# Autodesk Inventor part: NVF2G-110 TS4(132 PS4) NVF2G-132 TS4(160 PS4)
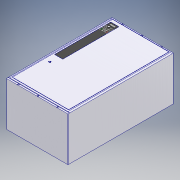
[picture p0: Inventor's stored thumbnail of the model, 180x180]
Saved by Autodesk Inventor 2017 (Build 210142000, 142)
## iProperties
Part Number: NVF2G-110 TS4(132 PS4) NVF2G-132 TS4(160 PS4)
Material: Типовые
Document SubType Name: Modeling
Designer: RSagdiev
Density: 1 g/cm^3
Appearance: По умолчанию
Author: RSagdiev
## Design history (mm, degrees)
sketch "Эскиз1"
  geometry: L1 (0, 0)-(44.679, 0) reference; L2 (0, 0)-(0, 56.035) reference; L3 (0, 0)-(807, 0); L4 (807, 0)-(807, 336.6); L5 (807, 336.6)-(0, 336.6); L6 (0, 336.6)-(0, 0)
  constraints: 12 end point, 3 horizontal, 2 parallel, 2 vertical, 1 perpendicular
  dimensions: "d0" = 807 distance of L5.end L4.end; "d1" = 336.6 distance of L4.end L3.end
extrude "Выдавливание1" new body sketch "Эскиз1" stored distance "d2" = 470; taper "d3" = 0 deg
sketch "Эскиз2"
  geometry: L1 (0, 0)-(0, 807) reference; L2 (470, 0)-(470, 807) reference; L3 (0, 807)-(150, 807); L4 (470, 807)-(470, 795); L5 (470, 0)-(320, 0); L6 (0, 0)-(0, 12); L7 (0, 807)-(470, 807) reference; L8 (0, 807)-(150, 807); L9 (150, 807)-(150, 795); L10 (150, 795)-(0, 795); L11 (0, 795)-(0, 807); L12 (470, 807)-(320, 807); L13 (320, 807)-(320, 795); L14 (320, 795)-(470, 795); L15 (470, 795)-(470, 807); L16 (0, 0)-(470, 0) reference; L17 (0, 0)-(150, 0); L18 (150, 0)-(150, 12); L19 (150, 12)-(0, 12); L20 (0, 12)-(0, 0); L21 (470, 0)-(320, 0); L22 (320, 0)-(320, 12); L23 (320, 12)-(470, 12); L24 (470, 12)-(470, 0); L25 (150, 807)-(320, 807); L26 (0, 795)-(0, 807); L27 (320, 807)-(470, 807); L28 (470, 795)-(470, 12); L29 (320, 0)-(150, 0); L30 (470, 12)-(470, 0); L31 (150, 0)-(0, 0); L32 (0, 12)-(0, 795); L33 (150, 795)-(320, 795); L34 (150, 12)-(320, 12); 1 further point
  constraints: 60 end point, 26 parallel, 13 perpendicular, 7 horizontal
  dimensions: "d4" = 150 distance of L9.end L10.end; "d5" = 12 distance of L3.end L9.end; "d6" = 150 distance of L4.end L13.end; "d7" = 12 distance of L13.end L12.end; "d8" = 150 distance of L6.end L18.end; "d9" = 12 distance of L18.end L17.end; "d10" = 150 distance of L22.end L23.end; "d11" = 12 distance of L5.end L22.end
extrude "Выдавливание2" new body sketch "Эскиз2" distance "d12" = 4; taper "d13" = 0 deg
sketch "Эскиз3"
  geometry: L1 (450, 25)-(450, 791); L2 (20, 791)-(450, 791); L3 (20, 791)-(20, 25); L4 (20, 791)-(450, 791); L5 (20, 25)-(450, 25); L6 (0, 795)-(0, 12) reference; L7 (470, 12)-(470, 795) reference; L8 (0, 807)-(470, 807) reference; L9 (0, 0)-(470, 0) reference; 1 further point
  constraints: 11 end point, 2 perpendicular, 1 horizontal
  dimensions: "d162" = 20 distance between parallel lines of L6 L3 (derived); "d164" = 20 distance between parallel lines of L7 L1; "d203" = 16 distance between parallel lines of L2 L8; "d204" = 25 distance between parallel lines of L9 L5
extrude "Выдавливание3" new body sketch "Эскиз3" distance "d17" = 2; taper "d18" = 0 deg
sketch "Эскиз4"
  geometry: L1 (91, 767)-(32, 767); L2 (30, 765)-(30, 339); L3 (32, 337)-(91, 337); L4 (93, 339)-(93, 765); L5 (0, 807)-(470, 807) reference; L6 (0, 795)-(0, 12) reference; A1 r 2 centre (32, 765) between (32, 767) and (30, 765); A2 r 2 centre (91, 765) between (93, 765) and (91, 767); A3 r 2 centre (91, 339) between (91, 337) and (93, 339); A4 r 2 centre (32, 339) between (30, 339) and (32, 337); 6 further points
  constraints: 8 end point, 8 point on circle, 8 tangent, 6 point on line, 4 centre point, 3 equal radius, 2 parallel, 1 horizontal, 1 perpendicular
  dimensions: "d20" = 63 distance of point (93, 337) point (30, 337); "d21" = 430 distance of point (30, 337) point (30, 767); "d24" = 2 radius of A1; "d165" = 40 distance between parallel lines of L5 L1; "d166" = 30 distance between parallel lines of L6 L2
extrude "Выдавливание4" cut sketch "Эскиз4" distance "d25" = 0.6; taper "d26" = 0 deg
sketch "Эскиз5"
  geometry: L1 (0, 807)-(470, 807) reference; L2 (0, 0)-(0, 807) reference; L3 (470, 807)-(470, 0) reference; L4 (0, 0)-(470, 0) reference; C1 r 5 at (85, 801); C2 r 5 at (235, 801); C3 r 5 at (85, 6); C4 r 5 at (235, 6); C5 r 5 at (385, 801); C6 r 5 at (385, 6); 1 further point
  constraints: 6 centre point
  dimensions: "d27" = 10 diameter of C1; "d28" = 6 distance from line of C1.centre L1; "d30" = 10 diameter of C2; "d31" = 6 distance from line of C2.centre L1; "d33" = 10 diameter of C3; "d34" = 6 distance from line of L4 C3.centre; "d36" = 10 diameter of C4; "d38" = 6 distance from line of C4.centre L4; "d169" = 150 distance of C1.centre C2.centre; "d172" = 150 distance of C4.centre C3.centre (derived); "d205" = 10 diameter of C5; "d206" = 150 distance of C5.centre C2.centre (derived); "d207" = 10 diameter of C6; "d208" = 150 distance of C6.centre C4.centre (derived); "d209" = 470 distance between parallel lines of L3 L2 (derived); "d210" = 85 distance from line of L2 C1.centre (derived); "d211" = 85 distance from line of L2 C3.centre (derived)
extrude "Выдавливание5" cut sketch "Эскиз5" stored distance "d39" = 0.6; taper "d40" = 0 deg
sketch "Эскиз6"
  geometry: L1 (30, 676)-(30, 732); L2 (91, 674)-(32, 674); L3 (93, 765)-(93, 732); L4 (32, 767)-(91, 767); L5 (30, 676)-(30, 765); L6 (30, 732)-(93, 732); L7 (93, 765)-(93, 732); L8 (30, 732)-(30, 765); L9 (93, 732)-(93, 676); L10 (43.5, 743)-(79.5, 743); L11 (81.5, 745)-(81.5, 755); L12 (79.5, 757)-(43.5, 757); L13 (41.5, 755)-(41.5, 745); L14 (41.5, 743)-(81.5, 757); L15 (81.5, 743)-(41.5, 757); L16 (61.5, 720.5)-(61.5, 685.857); L17 (53.25, 720.5)-(53.25, 685.857); L18 (69.75, 685.857)-(69.75, 720.5); L19 (47, 727)-(36, 727); L20 (35, 726)-(35, 715); L21 (36, 714)-(47, 714); L22 (48, 715)-(48, 726); L23 (48, 727)-(35, 714); L24 (35, 727)-(48, 714); L25 (81.5, 745)-(81.5, 680.5); L26 (41.5, 720.5)-(88.409, 720.5); L27 (39.654, 703.179)-(85.729, 703.179); L28 (39.654, 685.857)-(84.963, 685.857); L29 (88, 715)-(88, 726); L30 (76, 714)-(87, 714); L31 (88, 727)-(75, 714); L32 (75, 727)-(88, 714); L33 (75, 726)-(75, 715); L34 (87, 727)-(76, 727); L35 (88, 697.679)-(88, 708.679); L36 (76, 696.679)-(87, 696.679); L37 (88, 709.679)-(75, 696.679); L38 (75, 709.679)-(88, 696.679); L39 (75, 708.679)-(75, 697.679); L40 (87, 709.679)-(76, 709.679); L41 (88, 680.357)-(88, 691.357); L42 (76, 679.357)-(87, 679.357); L43 (88, 692.357)-(75, 679.357); L44 (75, 692.357)-(88, 679.357); L45 (75, 691.357)-(75, 680.357); L46 (87, 692.357)-(76, 692.357); L47 (48, 680.357)-(48, 691.357); L48 (36, 679.357)-(47, 679.357); L49 (48, 692.357)-(35, 679.357); L50 (35, 692.357)-(48, 679.357); L51 (35, 691.357)-(35, 680.357); L52 (47, 692.357)-(36, 692.357); L53 (48, 697.679)-(48, 708.679); L54 (36, 696.679)-(47, 696.679); L55 (48, 709.679)-(35, 696.679); L56 (35, 709.679)-(48, 696.679); L57 (35, 708.679)-(35, 697.679); L58 (47, 709.679)-(36, 709.679); L59 (91, 674)-(32, 674); L60 (0, 807)-(470, 807) reference; L61 (0, 793)-(0, 14); L62 (93, 732)-(93, 676); C1 r 6.5 at (61.5, 720.5); C2 r 6.5 at (61.5, 685.857); C3 r 6.5 at (61.5, 703.179); A1 r 2 centre (43.5, 755) between (43.5, 757) and (41.5, 755); A2 r 2 centre (79.5, 755) between (81.5, 755) and (79.5, 757); A3 r 2 centre (79.5, 745) between (79.5, 743) and (81.5, 745); A4 r 2 centre (43.5, 745) between (41.5, 745) and (43.5, 743); A5 r 8.25 centre (61.5, 720.5) between (69.75, 720.5) and (53.25, 720.5); A6 r 8.25 centre (61.5, 685.857) between (53.25, 685.857) and (69.75, 685.857); A7 r 1 centre (47, 726) between (48, 726) and (47, 727); A8 r 1 centre (47, 715) between (47, 714) and (48, 715); A9 r 1 centre (36, 715) between (35, 715) and (36, 714); A10 r 1 centre (36, 726) between (36, 727) and (35, 726); A11 r 1 centre (87, 715) between (87, 714) and (88, 715); A12 r 1 centre (87, 726) between (88, 726) and (87, 727); A13 r 1 centre (76, 726) between (76, 727) and (75, 726); A14 r 1 centre (76, 715) between (75, 715) and (76, 714); A15 r 1 centre (87, 697.679) between (87, 696.679) and (88, 697.679); A16 r 1 centre (87, 708.679) between (88, 708.679) and (87, 709.679); A17 r 1 centre (76, 708.679) between (76, 709.679) and (75, 708.679); A18 r 1 centre (76, 697.679) between (75, 697.679) and (76, 696.679); A19 r 1 centre (87, 680.357) between (87, 679.357) and (88, 680.357); A20 r 1 centre (87, 691.357) between (88, 691.357) and (87, 692.357); A21 r 1 centre (76, 691.357) between (76, 692.357) and (75, 691.357); A22 r 1 centre (76, 680.357) between (75, 680.357) and (76, 679.357); A23 r 1 centre (47, 680.357) between (47, 679.357) and (48, 680.357); A24 r 1 centre (47, 691.357) between (48, 691.357) and (47, 692.357); A25 r 1 centre (36, 691.357) between (36, 692.357) and (35, 691.357); A26 r 1 centre (36, 680.357) between (35, 680.357) and (36, 679.357); A27 r 1 centre (47, 697.679) between (47, 696.679) and (48, 697.679); A28 r 1 centre (47, 708.679) between (48, 708.679) and (47, 709.679); A29 r 1 centre (36, 708.679) between (36, 709.679) and (35, 708.679); A30 r 1 centre (36, 697.679) between (35, 697.679) and (36, 696.679); A31 r 2 centre (32, 765) between (32, 767) and (30, 765); A32 r 2 centre (91, 765) between (93, 765) and (91, 767); A33 r 2 centre (91, 676) between (91, 674) and (93, 676); A34 r 2 centre (32, 676) between (30, 676) and (32, 674); 15 further points
  constraints: 124 end point, 70 tangent, 68 point on circle, 67 point on line, 37 centre point, 21 equal radius, 15 midpoint, 15 parallel, 11 horizontal, 7 collinear, 7 perpendicular, 3 coincident, 2 vertical
  dimensions: "d43" = 35 distance between parallel lines of L4 L6; "d44" = 40 distance of L15.end L14.end; "d45" = 14 distance of L14.end L15.start; "d46" = 10 distance between parallel lines of L4 L12; "d47" = 2 radius of A1; "d48" = 11.5 distance between parallel lines of L8 L13; "d49" = 16.5 diameter of A6; "d50" = 31.5 distance between parallel lines of L1 L16; "d51" = 11.5 distance from line of L6 L16.start; "d52" = 11.85714 distance from line of L2 L16.end; "d53" = 13 diameter of C1; "d54" = 13 diameter of C2; "d55" = 13 diameter of C3; "d56" = 13 distance of L24.end L23.end; "d57" = 13 distance of L23.end L24.start; "d58" = 1 radius of A7 (derived); "d59" = 11.5 distance from line of L6 L26.start; "d60" = 11.5 distance from line of L5 L26.start; "d61" = 13 distance of L32.end L31.end; "d62" = 13 distance of L31.end L32.start; "d63" = 1 radius of A12 (derived); "d64" = 13 distance of L38.end L37.end; "d65" = 13 distance of L37.end L38.start; "d66" = 1 radius of A16 (derived); "d67" = 13 distance of L44.end L43.end; "d68" = 13 distance of L43.end L44.start; "d69" = 1 radius of A20 (derived); "d70" = 13 distance of L50.end L49.end; "d71" = 13 distance of L49.end L50.start; "d72" = 1 radius of A24 (derived); "d73" = 13 distance of L56.end L55.end; "d74" = 13 distance of L55.end L56.start; "d75" = 1 radius of A28 (derived); "d146" = 40 distance of point (81.5, 720.5) L26.start; "d147" = 4.32143 distance between parallel lines of L40 L30; "d148" = 4.32143 distance between parallel lines of L46 L36; "d149" = 93 distance between parallel lines of L2 L4; "d151" = 2 radius of A31; "d152" = 2 radius of A32; "d153" = 2 radius of A33; "d154" = 2 radius of A34; "d167" = 40 distance between parallel lines of L4 L60 (derived); "d168" = 30 distance between parallel lines of L61 L5 (derived)
extrude "Выдавливание6" new body sketch "Эскиз6" distance "d76" = 0.3; taper "d77" = 0 deg
extrude "Выдавливание7" new body sketch "Эскиз6" distance "d78" = 0.6; taper "d79" = 0 deg
sketch "Эскиз7"
  geometry: L1 (30, 732)-(93, 732) reference; L2 (30, 732)-(93, 732); L3 (93, 732)-(93, 732.1); L4 (93, 732.1)-(30, 732.1); L5 (30, 732.1)-(30, 732); 4 further points; 1 other entity
  constraints: 8 end point, 2 parallel, 1 horizontal, 1 perpendicular, 2 other
  dimensions: "d80" = 0.1 distance of L3.end L2.end
extrude "Выдавливание8" cut sketch "Эскиз7" distance "d81" = 0.3; taper "d82" = 0 deg
sketch "Эскиз8" dims "d91" = 10
  geometry: L1 (30, 732.1)-(93, 732.1) reference; C1 r 1 at (38, 737.1); C2 r 1 at (45.75, 737.1); C3 r 1 at (53.5, 737.1); C4 r 1 at (61.25, 737.1); C5 r 1 at (69, 737.1); C6 r 1 at (76.75, 737.1); C7 r 1 at (84.5, 737.1); 4 further points; 1 other entity
  constraints: 7 centre point, 1 horizontal, 13 other
  dimensions: "d83" = 2 diameter of C1; "d84" = 5 distance from line of C1.centre L1; "d85" = 8 dimension on C1.centre; "d88" = 7.75 distance of C1.centre C2.centre
extrude "Выдавливание9" join sketch "Эскиз8" distance "d93" = 0.3; taper "d94" = 0 deg
sketch "Эскиз9"
  geometry: C1 r 6.5 at (0, 0) reference; C2 r 7.5 at (0, 0); 1 further point
  constraints: 1 centre point, 1 coincident
  dimensions: "d95" = 15 diameter of C2
extrude "Выдавливание10" join sketch "Эскиз9" distance "d96" = 9.4; taper "d97" = -3 deg
sketch "Эскиз10"
  geometry: L1 (0, 7.331)-(0.619, 6.259); L2 (0.619, 6.259)-(-0.619, 6.259); L3 (-0.619, 6.259)-(0, 7.331); 2 further points
  constraints: 6 end point, 7 other
sketch "Эскиз11"
  geometry: L1 (0, 7.917)-(0.884, 6.386); L2 (0.884, 6.386)-(-0.884, 6.386); L3 (-0.884, 6.386)-(0, 7.917); 2 further points
  constraints: 6 end point, 7 other
feature "Лофт1" sketch "Эскиз10", "Эскиз11" dims "d98" = 0, "d99" = 90 deg, "d100" = 0, "d101" = 90 deg
sketch "Эскиз12"
  geometry: L1 (37.891, 721.651)-(44.111, 721.651); L2 (44.111, 721.651)-(44.111, 718.151); L3 (44.111, 718.151)-(37.891, 718.151); L4 (37.891, 718.151)-(37.891, 721.651); L5 (36.941, 704.552)-(45.796, 704.552); L6 (45.796, 704.552)-(45.796, 700.922); L7 (45.796, 700.922)-(36.941, 700.922); L8 (36.941, 700.922)-(36.941, 704.552); L9 (36.585, 687.216)-(45.942, 687.216); L10 (45.942, 687.216)-(45.942, 683.642); L11 (45.942, 683.642)-(36.585, 683.642); L12 (36.585, 683.642)-(36.585, 687.216); L13 (75.414, 687.216)-(86.966, 687.216); L14 (86.966, 687.216)-(86.966, 683.568); L15 (86.966, 683.568)-(75.414, 683.568); L16 (75.414, 683.568)-(75.414, 687.216); L17 (77.195, 704.434)-(85.389, 704.434); L18 (85.389, 704.434)-(85.389, 700.809); L19 (85.389, 700.809)-(77.195, 700.809); L20 (77.195, 700.809)-(77.195, 704.434); L21 (75.295, 721.77)-(88.345, 721.77); L22 (88.345, 721.77)-(88.345, 718.145); L23 (88.345, 718.145)-(75.295, 718.145); L24 (75.295, 718.145)-(75.295, 721.77); 1 further point
  constraints: 12 other
feature "Рельеф1" dims "d4" = 150, "d5" = 12, "d6" = 150, "d7" = 12, "d8" = 150, "d9" = 12, "d10" = 150, "d11" = 12, "d105" = 0.1, "d106" = 0
feature "Рельеф2" dims "d4" = 150, "d5" = 12, "d6" = 150, "d7" = 12, "d8" = 150, "d9" = 12, "d10" = 150, "d11" = 12, "d107" = 0.1, "d108" = 0
feature "Рельеф3" dims "d4" = 150, "d5" = 12, "d6" = 150, "d7" = 12, "d8" = 150, "d9" = 12, "d10" = 150, "d11" = 12, "d109" = 0.1, "d110" = 0
feature "Рельеф4" dims "d4" = 150, "d5" = 12, "d6" = 150, "d7" = 12, "d8" = 150, "d9" = 12, "d10" = 150, "d11" = 12, "d111" = 0.1, "d112" = 0
feature "Рельеф5" dims "d4" = 150, "d5" = 12, "d6" = 150, "d7" = 12, "d8" = 150, "d9" = 12, "d10" = 150, "d11" = 12, "d113" = 0.1, "d114" = 0
feature "Рельеф6" dims "d4" = 150, "d5" = 12, "d6" = 150, "d7" = 12, "d8" = 150, "d9" = 12, "d10" = 150, "d11" = 12, "d115" = 0.1, "d116" = 0
sketch "Эскиз13"
  geometry: L1 (-3.144, -2.347)-(-0.04, 3.728); L2 (-0.04, 3.728)-(3.298, -2.347); L3 (3.298, -2.347)-(2.096, -2.347); L4 (2.096, -2.347)-(-0.04, 1.541); L5 (-0.04, 1.541)-(-2.027, -2.347); L6 (-2.027, -2.347)-(-3.144, -2.347); L7 (-9.387, -8.657)-(8.031, -8.657); L8 (-3.144, -14.967)-(-0.04, -21.041); L9 (-0.04, -21.041)-(3.298, -14.967); L10 (3.298, -14.967)-(2.096, -14.967); L11 (2.096, -14.967)-(-0.04, -18.855); L12 (-0.04, -18.855)-(-2.027, -14.967); L13 (-2.027, -14.967)-(-3.144, -14.967); 1 further point
  constraints: 26 end point, 6 symmetric about line, 2 horizontal, 2 parallel, 2 point on line, 1 collinear
feature "Рельеф7" dims "d4" = 150, "d5" = 12, "d6" = 150, "d7" = 12, "d8" = 150, "d9" = 12, "d10" = 150, "d11" = 12, "d117" = 0.1, "d118" = 0
feature "Рельеф8" dims "d4" = 150, "d5" = 12, "d6" = 150, "d7" = 12, "d8" = 150, "d9" = 12, "d10" = 150, "d11" = 12, "d119" = 0.1, "d120" = 0
sketch "Эскиз14"
  geometry: L1 (62.079, 278.98)-(70.375, 264.61); L2 (70.375, 264.61)-(53.782, 264.61); L3 (53.782, 264.61)-(62.079, 278.98); L4 (68.948, 265.434)-(62.079, 277.332); L5 (62.079, 277.332)-(55.209, 265.434); L6 (55.209, 265.434)-(68.948, 265.434); L7 (61.252, 273.665)-(60.311, 269.855); L8 (60.311, 269.855)-(62.732, 270.025); L9 (62.732, 270.025)-(61.691, 267.709); L10 (61.691, 267.709)-(60.742, 268.135); L11 (60.742, 268.135)-(60.898, 265.905); L12 (60.898, 265.905)-(63.368, 266.954); L13 (63.368, 266.954)-(62.687, 267.261); L14 (62.687, 267.261)-(64.617, 270.896); L15 (64.617, 270.896)-(61.462, 270.713); L16 (61.462, 270.713)-(63.028, 273.665); L17 (63.028, 273.665)-(61.252, 273.665); 2 further points
  constraints: 34 end point, 2 perpendicular, 2 point on line, 1 parallel, 9 other
extrude "Выдавливание11" cut sketch "Эскиз14" distance "d121" = 0.8; taper "d122" = 0 deg
extrude "Выдавливание12" join sketch "Эскиз14" stored distance "d123" = 0.05; taper "d124" = 0 deg
sketch "Эскиз15"
  geometry: L1 (32.937, 740.995)-(57.215, 740.995); L2 (57.215, 740.995)-(57.215, 738.81); L3 (57.215, 738.81)-(32.937, 738.81); L4 (32.937, 738.81)-(32.937, 740.995); L5 (58.162, 740.617)-(88.881, 740.617); L6 (88.881, 740.617)-(88.881, 736.704); L7 (88.881, 736.704)-(58.162, 736.704); L8 (58.162, 736.704)-(58.162, 740.617); L9 (30, 732.1)-(93, 732.1) reference; C1 r 1 at (38, 737.1) reference; 7 further points; 2 other entities
  constraints: 6 other
  dimensions: "d155" = 0.71019 distance edge to line of C1 L3; "d156" = 2.93695 dimension on L4; "d157" = 4.60387 distance between parallel lines of L9 L7; "d158" = 4.11868 dimension on L6
feature "Рельеф9" sketch "Эскиз15" dims "d4" = 150, "d5" = 12, "d6" = 150, "d7" = 12, "d8" = 150, "d9" = 12, "d10" = 150, "d11" = 12, "d125" = 0.1, "d126" = 0
sketch "Эскиз17"
  geometry: L1 (54.534, 359)-(54.534, 352.001); L2 (54.534, 352.001)-(52.465, 352.001); L3 (52.465, 352.001)-(52.465, 359); L4 (52.465, 359)-(54.534, 359); 1 further point
  constraints: 2 other
feature "Рельеф10" sketch "Эскиз17" dims "d4" = 150, "d5" = 12, "d6" = 150, "d7" = 12, "d8" = 150, "d9" = 12, "d10" = 150, "d11" = 12, "d144" = 0.1, "d145" = 0
sketch "Эскиз19" dims "d179" = 10
  geometry: L1 (113.24, 333.958)-(134.375, 351.485); L2 (114.525, 332.409)-(135.66, 349.935); L3 (133.09, 353.034)-(111.955, 335.508); L4 (336.6, 795)-(336.6, 12) reference; L5 (113.24, 323.958)-(134.375, 341.485); L6 (114.525, 322.409)-(135.66, 339.935); L7 (133.09, 343.034)-(111.955, 325.508); L8 (113.24, 313.958)-(134.375, 331.485); L9 (114.525, 312.409)-(135.66, 329.935); L10 (133.09, 333.034)-(111.955, 315.508); L11 (113.24, 303.958)-(134.375, 321.485); L12 (114.525, 302.409)-(135.66, 319.935); L13 (133.09, 323.034)-(111.955, 305.508); L14 (113.24, 293.958)-(134.375, 311.485); L15 (114.525, 292.409)-(135.66, 309.935); L16 (133.09, 313.034)-(111.955, 295.508); L17 (113.24, 283.958)-(134.375, 301.485); L18 (114.525, 282.409)-(135.66, 299.935); L19 (133.09, 303.034)-(111.955, 285.508); L20 (113.24, 273.958)-(134.375, 291.485); L21 (114.525, 272.409)-(135.66, 289.935); L22 (133.09, 293.034)-(111.955, 275.508); L23 (113.24, 263.958)-(134.375, 281.485); L24 (114.525, 262.409)-(135.66, 279.935); L25 (133.09, 283.034)-(111.955, 265.508); L26 (113.24, 253.958)-(134.375, 271.485); L27 (114.525, 252.409)-(135.66, 269.935); L28 (133.09, 273.034)-(111.955, 255.508); L29 (113.24, 243.958)-(134.375, 261.485); L30 (114.525, 242.409)-(135.66, 259.935); L31 (133.09, 263.034)-(111.955, 245.508); A1 r 2.013 centre (113.24, 333.958) between (111.955, 335.508) and (114.525, 332.409); A2 r 2.013 centre (134.375, 351.485) between (135.66, 349.935) and (133.09, 353.034); A3 r 2.013 centre (113.24, 323.958) between (111.955, 325.508) and (114.525, 322.409); A4 r 2.013 centre (134.375, 341.485) between (135.66, 339.935) and (133.09, 343.034); A5 r 2.013 centre (113.24, 313.958) between (111.955, 315.508) and (114.525, 312.409); A6 r 2.013 centre (134.375, 331.485) between (135.66, 329.935) and (133.09, 333.034); A7 r 2.013 centre (113.24, 303.958) between (111.955, 305.508) and (114.525, 302.409); A8 r 2.013 centre (134.375, 321.485) between (135.66, 319.935) and (133.09, 323.034); A9 r 2.013 centre (113.24, 293.958) between (111.955, 295.508) and (114.525, 292.409); A10 r 2.013 centre (134.375, 311.485) between (135.66, 309.935) and (133.09, 313.034); A11 r 2.013 centre (113.24, 283.958) between (111.955, 285.508) and (114.525, 282.409); A12 r 2.013 centre (134.375, 301.485) between (135.66, 299.935) and (133.09, 303.034); A13 r 2.013 centre (113.24, 273.958) between (111.955, 275.508) and (114.525, 272.409); A14 r 2.013 centre (134.375, 291.485) between (135.66, 289.935) and (133.09, 293.034); A15 r 2.013 centre (113.24, 263.958) between (111.955, 265.508) and (114.525, 262.409); A16 r 2.013 centre (134.375, 281.485) between (135.66, 279.935) and (133.09, 283.034); A17 r 2.013 centre (113.24, 253.958) between (111.955, 255.508) and (114.525, 252.409); A18 r 2.013 centre (134.375, 271.485) between (135.66, 269.935) and (133.09, 273.034); A19 r 2.013 centre (113.24, 243.958) between (111.955, 245.508) and (114.525, 242.409); A20 r 2.013 centre (134.375, 261.485) between (135.66, 259.935) and (133.09, 263.034); 13 further points
  constraints: 80 end point, 40 point on circle, 20 centre point, 4 tangent, 1 midpoint, 1 parallel, 1 vertical, 108 other
  dimensions: "d176" = 10 distance of L2.start L6.start
extrude "Выдавливание14" cut sketch "Эскиз19" distance "d181" = 10; taper "d182" = 0 deg
sketch "Эскиз20" dims "d191" = 10, "d198" = 10
  geometry: L1 (336.6, 2)-(0, 2) reference; L2 (0, 807)-(0, 0) reference; C1 r 2 at (15, 132); C2 r 2 at (20, 132); C3 r 2 at (25, 132); C4 r 2 at (30, 132); C5 r 2 at (35, 132); C6 r 2 at (40, 132); C7 r 2 at (45, 132); C8 r 2 at (50, 132); C9 r 2 at (55, 132); C10 r 2 at (60, 132); C11 r 2 at (65, 132); C12 r 2 at (70, 132); C13 r 2 at (70, 127); C14 r 2 at (65, 127); C15 r 2 at (60, 127); C16 r 2 at (55, 127); C17 r 2 at (15, 127); C18 r 2 at (20, 127); C19 r 2 at (25, 127); C20 r 2 at (30, 127); C21 r 2 at (35, 127); C22 r 2 at (40, 127); C23 r 2 at (45, 127); C24 r 2 at (50, 127); C25 r 2 at (70, 122); C26 r 2 at (65, 122); C27 r 2 at (60, 122); C28 r 2 at (55, 122); C29 r 2 at (15, 122); C30 r 2 at (20, 122); C31 r 2 at (25, 122); C32 r 2 at (30, 122); C33 r 2 at (35, 122); C34 r 2 at (40, 122); C35 r 2 at (45, 122); C36 r 2 at (50, 122); C37 r 2 at (70, 117); C38 r 2 at (65, 117); C39 r 2 at (60, 117); C40 r 2 at (55, 117); C41 r 2 at (15, 117); C42 r 2 at (20, 117); C43 r 2 at (25, 117); C44 r 2 at (30, 117); C45 r 2 at (35, 117); C46 r 2 at (40, 117); C47 r 2 at (45, 117); C48 r 2 at (50, 117); C49 r 2 at (70, 112); C50 r 2 at (65, 112); C51 r 2 at (60, 112); C52 r 2 at (55, 112); C53 r 2 at (15, 112); C54 r 2 at (20, 112); C55 r 2 at (25, 112); C56 r 2 at (30, 112); C57 r 2 at (35, 112); C58 r 2 at (40, 112); C59 r 2 at (45, 112); C60 r 2 at (50, 112); C61 r 2 at (70, 107); C62 r 2 at (65, 107); C63 r 2 at (60, 107); C64 r 2 at (55, 107)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; 1 further point
  constraints: 240 centre point, 1 horizontal, 1 vertical, 478 other
  dimensions: "d183" = 4 diameter of C1; "d184" = 15 distance from line of L2 C1.centre; "d185" = 130 distance from line of L1 C1.centre; "d188" = 5 distance of C1.centre C2.centre; "d195" = 5 distance of C12.centre C13.centre
extrude "Выдавливание15" cut sketch "Эскиз20" distance "d200" = 15; taper "d201" = 0 deg
fillet "Сопряжение3" dims "d212" = 20
fillet "Сопряжение4" dims "d213" = 2
node "Твердое тело1"
pattern_circular "Круговой массив1" dims angle "d103" = 360 deg
node "Твердое тело2"
node "Твердое тело3"
node "Твердое тело4"
node "Твердое тело5"
